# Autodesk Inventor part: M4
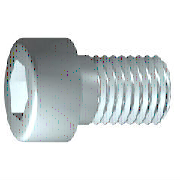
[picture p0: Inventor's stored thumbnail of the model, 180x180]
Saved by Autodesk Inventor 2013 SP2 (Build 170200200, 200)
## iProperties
IsCustomPart: 0
Created: 2016-04
Part Number: M4
Material: 강철, 연강
Description: 6각머리 태핑 나사
Document SubType Name: Modeling
Standard: KS B 1003
Designer: mdu
Standards Organization: KS
Language: ko-KR
Size Designation: M 4 x 10
Categories: <MemberInstance><Categories><Category DisplayName="조임쇠" InternalName="e4da775c-781d-43d5-af7c-5136215cf5a6" Mnemonic="FSTN"><Category DisplayName="볼트" InternalN
Density: 7.86 g/cm^3
Mass: 2.0371 g
Surface Area: 3.0572 cm^2
Volume: 0.259174 cm^3
Author: mdu
Revision Number: 1
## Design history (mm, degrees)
sketch "스케치1"
  geometry: L1 (-1, 0)-(10, 0); L2 (10, 0)-(10, 2); L3 (10, 2)-(1.75, 2); L4 (1.75, 2)-(1.32, 2); L5 (1.32, 2)-(0, 2); L6 (0, 2)-(0, 3.5); L7 (0, 3.5)-(-4, 3.5); L8 (-4, 3.5)-(-4, 1.732); L9 (-4, 1.732)-(-2, 1.732); L10 (-2, 1.732)-(-1, 0); L11 (-6.8, 0)-(12.8, 0) reference; L12 (0, -0.7)-(0, 4.2) reference; L13 (1.75, 2)-(0, 2)
  constraints: 22 end point, 6 parallel, 2 collinear, 2 perpendicular, 1 horizontal, 1 point on line
  dimensions: "d1" = 8.25 distance from line of L3.end L2 (= GEL); "d2" = 0.42952 distance of L4.end L3.end (computed from GAL); "d3" = 4 distance between parallel lines of L8 L6 (= KOH); "d4" = 2 distance of L8.end L9.end (= INTI); "d5" = 60 deg angle of L10 L1; "d6" = 4 diameter of L3 L1 (= GD); "d7" = 4 diameter of L5 L1 (= BDM); "d8" = 3.4641 diameter of L9 L1 (= 1.1547 x SW); "d9" = 7 diameter of L7 L1 (= KOD); "d26" = 10 distance between parallel lines of L12 L2 (= NLG)
revolve "본체" sketch "스케치1" stored, may be unused: angle "d10" = 90 deg
sketch "스케치2"
  geometry: L1 (0, -4.9)-(0, 4.9) reference; L2 (-4.9, 0)-(4.9, 0) reference; L3 (1.732, 0)-(0.866, -1.5); L4 (0.866, -1.5)-(-0.866, -1.5); L5 (-0.866, -1.5)-(-1.732, 0); L6 (-1.732, 0)-(-0.866, 1.5); L7 (-0.866, 1.5)-(0.866, 1.5); L8 (0.866, 1.5)-(1.732, 0); 2 further points
  constraints: 12 end point, 1 coincident, 1 horizontal alignment, 1 point on line, 12 other
extrude "슬롯" join sketch "스케치2" stored distance "d11" = 10; taper "d12" = 0 deg
workplane "Work Plane1"
fillet "Fillet2" dims "d30" = 0.1 (= R)
body "Solid1"
fillet "모깎기1" dims "d17" = 0.4 (= RR)
feature "스레드" dims "d13" = 8.25 (= GEL), "d14" = 0
chamfer "모따기1" distance "d15" = 0.42941 (= -0.5 x SPD + 0.5 x GD); stored, may be unused: second distance "d16" = 0.42941 (= GUL), angle "d27" = 45 deg
other parameters: "GD" = 4 (= NND) [user parameter; used in 2 equation terms], "NLG" = 10 [user parameter; used in 1 equation term], "GEL" = 8.25 [user parameter; used in 2 equation terms], "KOD" = 7 [user parameter; used in 1 equation term], "KOH" = 4 [user parameter; used in 1 equation term], "INTI" = 2 [user parameter; used in 1 equation term], "GAL" = 0.42941 (= 0.61345 x PTC) [user parameter; used in 1 equation term], "GUL" = 0.42941 (= 0.61345 x PTC) [user parameter; used in 1 equation term], "BDM" = 4 (= NND) [user parameter; used in 1 equation term], "SW" = 3 [user parameter; used in 2 equation terms], "RR" = 0.4 [user parameter; used in 1 equation term], "SPD" = 3.14117 (= NND - 1.2269 x PTC) [user parameter; used in 1 equation term], "d19" = 0, "d28" = 0, "d29" = 0, "R" = 0.1 [user parameter; used in 1 equation term], "PHH" = 0.2 [user parameter], "GD1" = 3.14117 (= THREADDIA - 1.2269 x PTC) [user parameter], "THREADDIA" = 4 [user parameter; used in 1 equation term], "FAWI" = 45 deg [user parameter], "TPU" = 14.28571 (computed from PTC) [user parameter], "PTC" = 0.7 [user parameter; used in 5 equation terms], "NND" = 4 [user parameter; used in 3 equation terms], "TOA" = 30 deg [user parameter], "E0" = 3.465 (= 1.155 x SW) [user parameter]
